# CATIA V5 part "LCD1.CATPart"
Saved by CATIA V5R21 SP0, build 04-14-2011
Part number: LCD
Bounding box of the stored display mesh (mm): x -92.8 to 92.8, y -50 to 50, z 0 to 2.8
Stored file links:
  C:\Users\Pouria\Desktop\Box\LCD1.CATPart
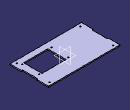
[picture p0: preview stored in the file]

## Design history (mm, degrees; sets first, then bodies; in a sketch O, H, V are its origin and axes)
Body1 (main body)
  Sketch1 on xy-plane, origin (0, 0, 0), H (1, 0, 0), V (0, 1, 0)
    line L1 (92.8, 50) -> (92.8, 20)
    line L2 (92.8, -50) -> (-92.8, -50)
    line L3 (-92.8, -50) -> (-92.8, -20)
    line L4 (-92.8, 50) -> (92.8, 50)
    point P1 (92.8, 50)
    point P2 (92.8, -50)
    line L5 (9.8, 13) -> (72.8, 13)
    line L6 (72.8, 13) -> (72.8, -35)
    line L7 (72.8, -35) -> (9.8, -35)
    line L8 (9.8, -35) -> (9.8, 13)
    line L9 (92.8, 20) -> (90, 20)
    line L10 (90, 20) -> (90, -20)
    line L11 (90, -20) -> (92.8, -20)
    point P12 (92.8, -20)
    point P13 (-92.8, 20)
    line L12 (-92.8, 20) -> (-90, 20)
    line L13 (-90, 20) -> (-90, -20)
    line L14 (-90, -20) -> (-92.8, -20)
    line L15 (92.8, -20) -> (92.8, -50)
    line L16 (-92.8, 20) -> (-92.8, 50)
    circle A1 centre (82.5, -42.5) radius 1.5
    point P17 (82.5, -42.5)
    circle A2 centre (82.5, 42.5) radius 1.5
    point P18 (82.5, 42.5)
    circle A3 centre (-82.5, 42.5) radius 1.5
    point P19 (-82.5, 42.5)
    circle A4 centre (-82.5, -42.5) radius 1.5
    point P20 (-82.5, -42.5)
    length L4 = 185.6
    length L5 = 63
    length L6 = 48
    distance L2 L7 = 15
    length L9 = 2.8
    length L13 = 40
    distance P1 P2 = 100
    distance L1 L6 = 20
    distance P17 L2 = 7.5
    distance P17 L10 = 7.5
    distance P20 L13 = 7.5
    distance P20 L2 = 7.5
    distance P19 L4 = 7.5
    distance P19 L13 = 7.5
    distance P18 L4 = 7.5
    distance P18 L10 = 7.5
    radius A2 = 1.5
    radius A3 = 1.5
    radius A4 = 1.5
    radius A1 = 1.5
    vertical: L1 V, L3 V, L6 V, L8 V, L10 V, L13 V, L15 V, L16 V
    horizontal: L2 H, L4 H, L5 H, L7 H, L9 H, L11 H, L12 H, L14 H
    equidistance: L1 L3 O, L2 L4 O
    coincidence: P12 L1, P13 L3, L9 L12, L11 L14, L1 L15, L3 L16
    symmetry: L12 L14 H, L11 L9 H, L10 L13 V
  Pad1: profile Sketch1, direction (0, 0, 1), length 2.8
  Sketch2 on end face of Pad1, origin (0, 0, 2.8), H (1, 0, 0), V (0, 1, 0)
    circle A1 centre (77.9, 10.95) radius 1.6
    point P1 (77.9, 10.95)
    circle A2 centre (77.9, -32.95) radius 1.6
    point P2 (77.9, -32.95)
    circle A3 centre (2, -32.95) radius 1.6
    point P3 (2, -32.95)
    circle A4 centre (2, 10.95) radius 1.6
    point P4 (2, 10.95)
    radius A1 = 1.6
    radius A2 = 1.6
    radius A3 = 1.6
    radius A4 = 1.6
    distance P4 V = 2
    distance P4 H = 10.95
    distance P3 V = 2
    distance P3 H = 32.95
    distance P1 V = 77.9
    distance P1 H = 10.95
    distance P2 V = 77.9
    distance P2 H = 32.95
  Pocket1: profile Sketch2, direction (0, 0, -1), through (limit type 3)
